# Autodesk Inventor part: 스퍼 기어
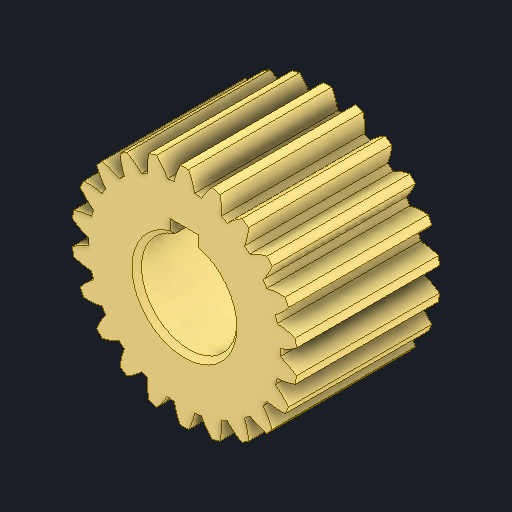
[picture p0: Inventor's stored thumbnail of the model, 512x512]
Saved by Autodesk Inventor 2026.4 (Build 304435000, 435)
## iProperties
Created: 2026-09
Part Number: 스퍼 기어
Material: 강철, 합금
Document SubType Name: Modeling
Designer: user
Density: 7.73 g/cm^3
Appearance: 기본값
Sending System: Autodesk Inventor 2027
Preprocessor: ST-DEVELOPER v20.1
Author: jhkim
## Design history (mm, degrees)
feature "Solid1"
node "솔리드1"
